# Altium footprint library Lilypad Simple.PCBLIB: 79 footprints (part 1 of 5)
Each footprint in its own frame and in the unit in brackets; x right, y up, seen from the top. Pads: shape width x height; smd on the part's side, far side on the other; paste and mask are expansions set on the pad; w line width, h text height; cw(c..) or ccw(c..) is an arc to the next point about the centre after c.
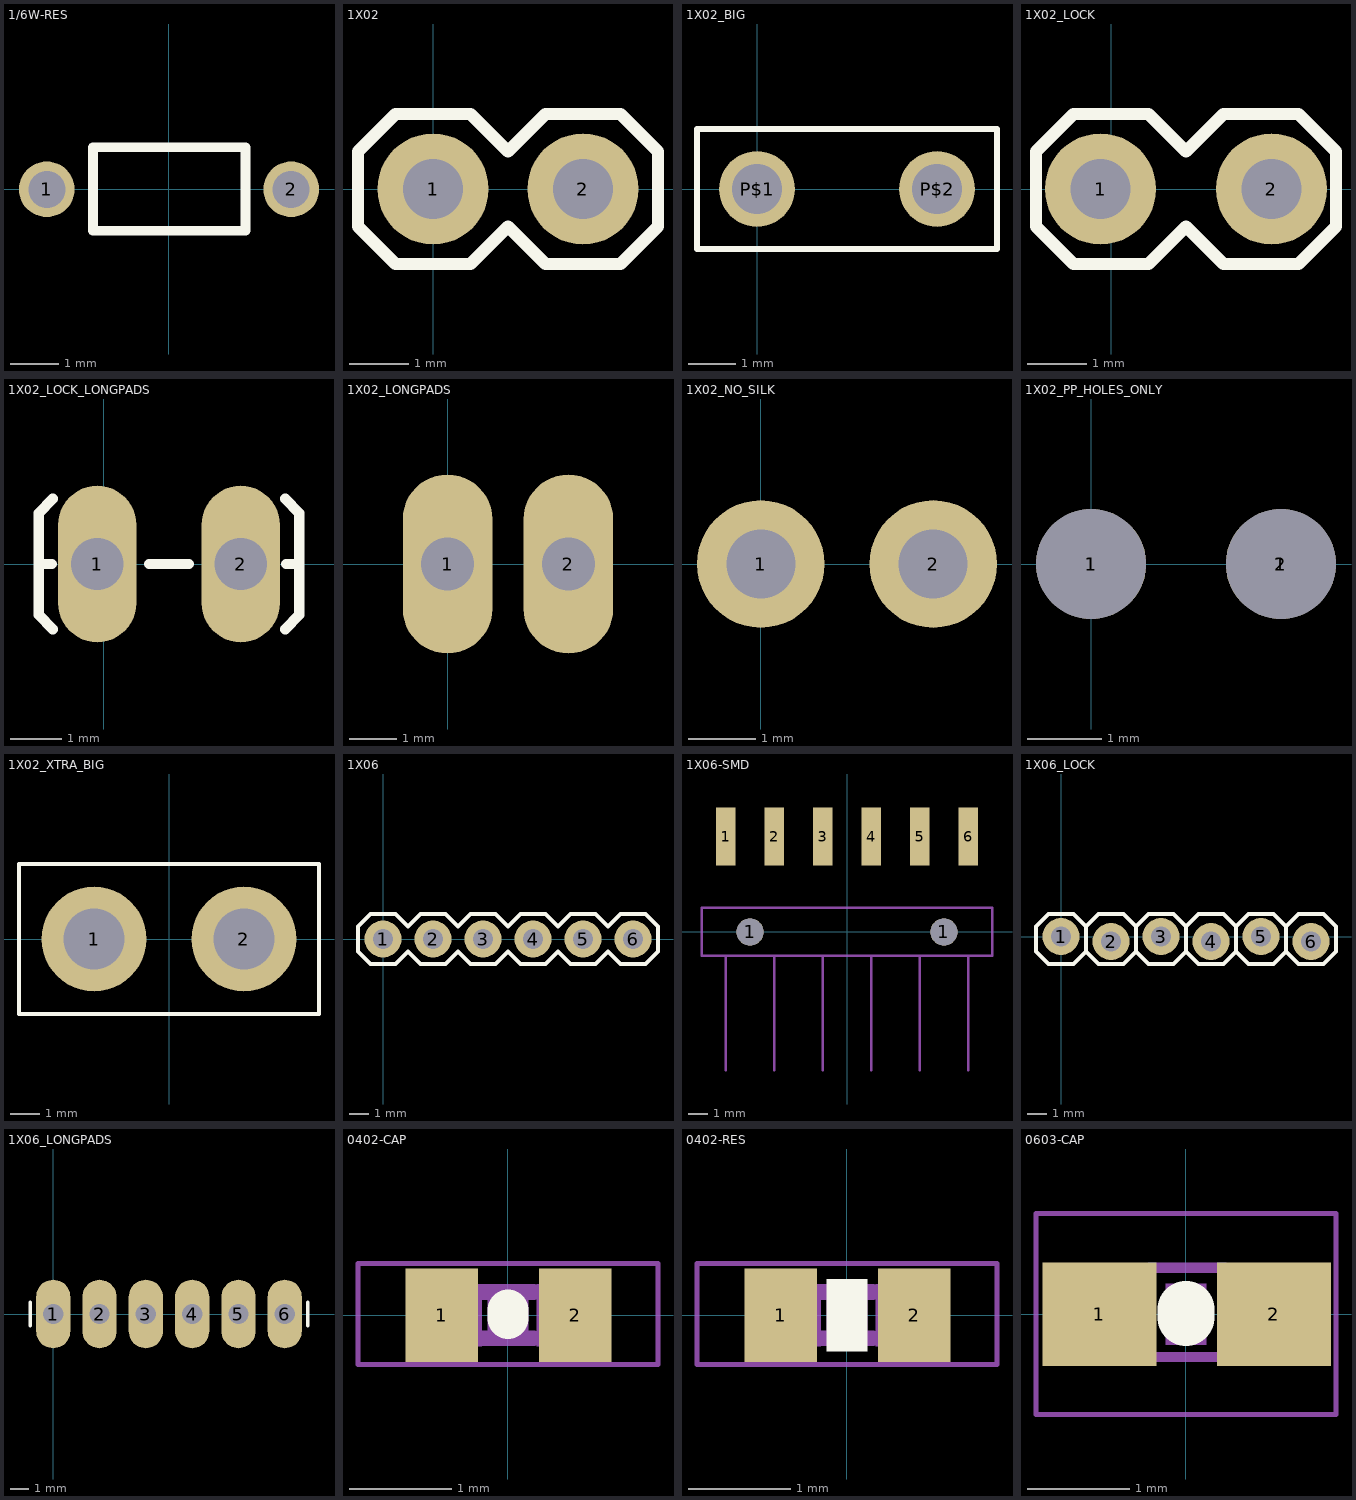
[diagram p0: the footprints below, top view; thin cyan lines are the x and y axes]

## 1/6W-RES [mil]
pads (2):
  round 45 hole 30: 1(-98.43,0) 2(99,0)
Top Overlay:
  lines w8: -61.02,-33.46 -61.02,34 62,34 62,-33.46 -61.02,-33.46

## 1X02 [mil]
pads (2):
  round 74 hole 40: 1(0,0) 2(100,0)
Top Overlay:
  lines w8: -50,-25 -50,25 -25,50 25,50 50,25 75,50 125,50 150,25 150,-25 125,-50 75,-50 50,-25 25,-50 -25,-50 -50,-25
Courtyard Bottom:
  rectangle: 90,-10 110,10
  rectangle: -10,-10 10,10

## 1X02_BIG [mil]
pads (2):
  round 63 hole 42: P$1(0,0) P$2(150,0)
Top Overlay:
  lines w5: -50,-50 -50,50 200,50 200,-50 -50,-50

## 1X02_LOCK [mil]
pads (2):
  round 74 hole 40: 1(-7,0) 2(107,0)
Top Overlay:
  lines w8: -50,-25 -50,25 -25,50 25,50 50,25 75,50 125,50 150,25 150,-25 125,-50 75,-50 50,-25 25,-50 -25,-50 -50,-25
Courtyard Bottom:
  rectangle: -11.5,-11.5 12,12
  rectangle: 89,-11.5 112,12

## 1X02_LOCK_LONGPADS [mil]
pads (2):
  oval 60x120 hole 40: 1(-5,0) 2(105,0)
Top Overlay:
  lines w8: -40,0 -50,0 ; -39,-50 -50,-39 -50,0 ; -39,50 -50,39 -50,0 ; 35,0 65,0 ; 139,-50 150,-39 150,0 ; 139,50 150,39 150,0 ; 140,0 150,0
Courtyard Bottom:
  rectangle: -11.5,-11.5 12,12
  rectangle: 89,-11.5 112,12

## 1X02_LONGPADS [mil]
pads (2):
  oval 74x148 hole 44: 1(0,0) 2(100,0)

## 1X02_NO_SILK [mil]
pads (2):
  round 74 hole 40: 1(0,0) 2(100,0)
Courtyard Bottom:
  rectangle: 90,-10 110,10
  rectangle: -10,-10 10,10

## 1X02_PP_HOLES_ONLY [mil]
pads (4):
  round 32 hole 35: 1(0,0) 2(100,0)
  round 58 hole 58: 1(0,0) 1(100,0)
Courtyard Bottom:
  circle w5: c0,0 r25
  circle w5: c100,0 r25

## 1X02_XTRA_BIG [mil]
pads (2):
  round 140 hole 81: 1(-100,0) 2(100,0)
Top Overlay:
  lines w5: -200,-100 -200,100 200,100 200,-100 -200,-100

## 1X06 [mil]
pads (6):
  round 74 hole 40: 1(0,0) 2(100,0) 3(200,0) 4(300,0) 5(400,0) 6(500,0)
Top Overlay:
  lines w8: -50,-25 -50,25 -25,50 25,50 50,25 75,50 125,50 150,25 175,50 225,50 250,25 275,50 325,50 350,25 375,50 425,50 450,25 475,50 525,50 550,25 550,-25 525,-50 475,-50 450,-25 425,-50 375,-50 350,-25 325,-50 275,-50 250,-25 225,-50 175,-50 150,-25 125,-50 75,-50 50,-25 25,-50 -25,-50 -50,-25
Courtyard Bottom:
  rectangle: 490,-10 510,10
  rectangle: 390,-10 410,10
  rectangle: 290,-10 310,10
  rectangle: 190,-10 210,10
  rectangle: 90,-10 110,10
  rectangle: -10,-10 10,10

## 1X06-SMD [mil]
pads (8):
  rect 40x119 smd: 1(-250,197) 2(-150,197) 3(-50,197) 4(50,197) 5(150,197) 6(250,197)
  round 56 hole 56: 1(-200,0) 1(200,0)
Courtyard Bottom:
  lines w5: -250,-285.43 -250,-49.21 ; -150,-285.43 -150,-49.21 ; -50,-285.43 -50,-49.21 ; 50,-285.43 50,-49.21 ; 150,-285.43 150,-49.21 ; 250,-285.43 250,-49.21 ; -250,-49.21 -300,-49.21 -300,50 300,50 300,-49.21 250,-49.21 ; -250,-49.21 -150,-49.21 ; -150,-49.21 -50,-49.21 ; -50,-49.21 50,-49.21 ; 50,-49.21 150,-49.21 ; 150,-49.21 250,-49.21

## 1X06_LOCK [mil]
pads (6):
  round 74 hole 40: 1(0,0) 2(100,-10) 3(200,0) 4(300,-10) 5(400,0) 6(500,-10)
Top Overlay:
  lines w8: 50,-30 75,-55 125,-55 150,-30 ; 50,-30 25,-55 -25,-55 -50,-30 -50,20 -25,45 25,45 50,20 ; 50,-30 50,20 ; 50,20 75,45 125,45 150,20 ; 150,-30 175,-55 225,-55 250,-30 ; 150,-30 150,20 ; 150,20 175,45 225,45 250,20 ; 250,-30 275,-55 325,-55 350,-30 ; 250,-30 250,20 ; 250,20 275,45 325,45 350,20 ; 350,-30 375,-55 425,-55 450,-30 ; 350,-30 350,20 ; 350,20 375,45 425,45 450,20 ; 450,-30 475,-55 525,-55 550,-30 550,20 525,45 475,45 450,20 ; 450,-30 450,20
Courtyard Bottom:
  rectangle: -11.5,-16.5 12,7
  rectangle: 89,-16.5 112,7
  rectangle: 189,-16.5 212,7
  rectangle: 289,-16.5 312,7
  rectangle: 389,-16.5 412,7
  rectangle: 489,-16.5 512,7

## 1X06_LONGPADS [mil]
pads (6):
  oval 74x148 hole 44: 1(0,0) 2(100,0) 3(200,0) 4(300,0) 5(400,0) 6(500,0)
Top Overlay:
  lines w8: -50,-25 -50,25 ; 550,-25 550,25
Courtyard Bottom:
  rectangle: 490,-10 510,10
  rectangle: 390,-10 410,10
  rectangle: 290,-10 310,10
  rectangle: 190,-10 210,10
  rectangle: 90,-10 110,10
  rectangle: -10,-10 10,10

## 0402-CAP [mil]
pads (2):
  rect 28x36 smd: 1(-25.59,0) 2(26,0)
Top Overlay:
  lines w16: 0,-1.2 0,2
Assembly Text Top:
  rectangle: -7.87,-11.81 8,12
Courtyard Bottom:
  rectangle: -21.81,-12 -10,12
  rectangle: 11,-12 22,12
  lines w6: -9.65,-8.82 10,-8.82 ; -9.65,9 10,9
Mechanical 37:
  lines w2: -57.99,-19.02 58,-19.02 58,20 -57.99,20 -57.99,-19.02

## 0402-RES [mil]
pads (2):
  rect 28x36 smd: 1(-25.59,0) 2(26,0)
Top Overlay:
  rectangle: -8,-14 8,14
Assembly Text Top:
  rectangle: -7.87,-11.81 8,12
Courtyard Bottom:
  rectangle: -21.81,-12 -10,12
  rectangle: 11,-12 22,12
  lines w6: -9.65,-8.82 10,-8.82 ; -9.65,9 10,9
Mechanical 37:
  lines w2: -57.99,-19.02 58,-19.02 58,20 -57.99,20 -57.99,-19.02

## 0603-CAP [mil]
pads (2):
  rect 44x40 smd: 1(-33.46,0) 2(34,0)
Top Overlay:
  lines w22: 0,-1.2 0,2
Assembly Text Top:
  rectangle: -7.87,-11.81 8,12
Courtyard Bottom:
  rectangle: -33,-18.5 -13.31,19
  rectangle: 13,-18.5 33,19
  lines w4: -14.02,-16.5 15,-16.5 ; -14.02,18 15,18
Mechanical 37:
  lines w2: -57.99,-38.7 58,-38.7 58,39 -57.99,39 -57.99,-38.7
